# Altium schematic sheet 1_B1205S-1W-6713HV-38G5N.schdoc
size 289 x 200 mm; Name: default297x210; Symbol: default297x210; Device: default297x210; Date: 2025.07.04; Rev: V1.1; Size: "A4"; Id: /; File: B1205S-1W-6713HV-38G5N; Sheet: /; @Page No: 1; @Page Count: 1; @Schematic Name: B1205S-1W-6713HV-38G5N; @Project Name: 全桥隔离电源-B1205S-1W-6713HV-38G5N; @Board Name: B1205S-1W-6713HV-38G5N; @Update Date: 2025-07-04; @Create Time: 17:14:56; @Update Time: 14:46:35; @Page Name: B1205S-1W-6713HV-38G5N; @Create Date: 2025-06-24
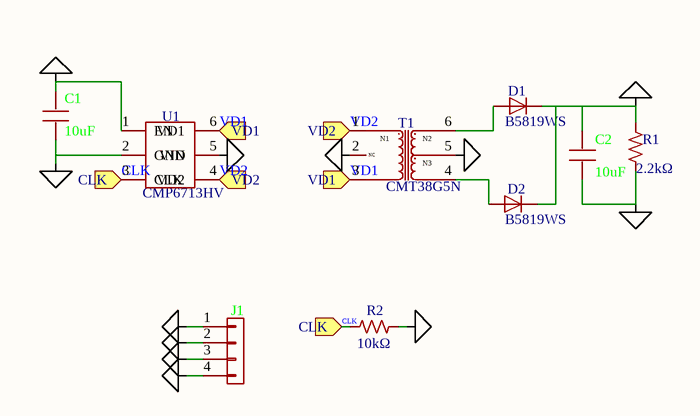
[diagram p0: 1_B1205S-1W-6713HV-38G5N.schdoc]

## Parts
C1  10uF  [C0603]
C2  10uF  [C0603]
D1  B5819WS  [SOD-323_L1.8-W1.3-LS2.5-RD]
D2  B5819WS  [SOD-323_L1.8-W1.3-LS2.5-RD]
J1  Connector_Generic_Conn_01x04  [coileasy:PinHeader_01x04_P2.54mm_Vertical]  (value not drawn)
R1  2.2kΩ  [R0603]
R2  10kΩ  [R0603]
T1  CMT38G5N  [coileasy:CMT38xxx]
U1  CMP6713HV  [coileasy:SOT-23-6]

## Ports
CLK (in), VD1 (in), VD2 (in)

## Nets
0V: C2.1 J1.3 R1.2 T1.5
+VO: C2.2 D1.1 D2.1 J1.4 R1.1
GND: C1.1 J1.1 R2.2 U1.2(GND)
VIN: C1.2 J1.2 T1.2 U1.1(EN) U1.5(VIN)
CLK: R2.1 U1.3(CLK) ; port CLK
VD1: T1.3 U1.6(VD1) ; port VD1
VD2: T1.1 U1.4(VD2) ; port VD2
NetD1_2: D1.2 T1.6
NetD2_2: D2.2 T1.4

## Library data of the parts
C1 = 0603X106M250NT: Manufacturer: FH(风华); Symbol: My_Library_C; Add into BOM: yes; Tolerance: ±20%; Voltage Rating: 25V; Temperature Coefficient: X5R
C2 = 0603X106K100NT: Manufacturer: FH(风华); Symbol: My_Library_C; Add into BOM: yes; Tolerance: ±10%; Voltage Rated: 10V; Temperature Coefficient: X5R
D1 D2 = B5819WS_C64886: Manufacturer: MDD(辰达半导体); Symbol: My_Library_D; Add into BOM: yes; Diode Configuration: 独立式; Forward Voltage (Vf@If): 900mV@3A; Reverse Voltage (Vr): 40V; Rectified Current: 1A; Reverse Leakage Current (Ir): 1mA@40V
J1 = Connector_Generic_Conn_01x04: Users: REF**; ki_fp_filters: Connector*:*_1x??_*; Add into BOM: yes
R1 = RC0603FR-072K2L: Manufacturer: YAGEO(国巨); Symbol: R; Add into BOM: yes; Tolerance: ±1%; Power(Watts): 100mW; Voltage-Supply(Max): 75V; Temperature Coefficient: ±100ppm/℃
R2 = RC0603FR-0710KL: Manufacturer: YAGEO(国巨); Symbol: R; Add into BOM: yes; Tolerance: ±1%; Power(Watts): 100mW; Overload Voltage (Max): 75V; Temperature Coefficient: ±100ppm/℃
T1 = CMT38G5N: Manufacturer: coileasy(线易); Symbol: MYLibrary _CMT38xxxx; Add into BOM: yes
U1 = CMP6713HV: Manufacturer: coileasy(线易); Symbol: MYLibrary_CMP6xxxx; Add into BOM: yes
